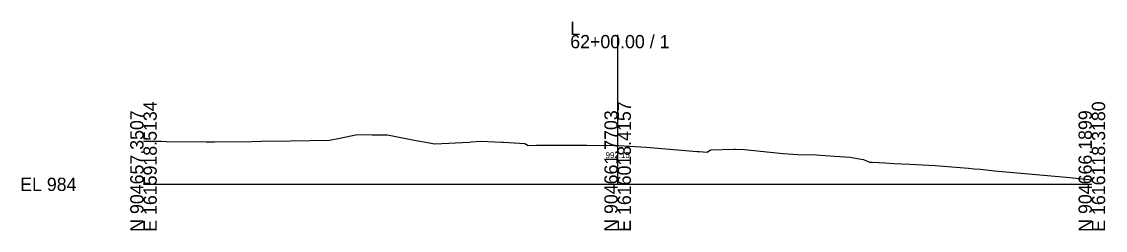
# Model space of a CAD drawing. Extents: x 1009 to 7438, y -1586 to 7964.
# Drawn here: x 6009.2 to 6237.7, y -86 to -42 of the extents above; entities that cross this region are included whole.
import ezdxf

# ---------------------------------------------------------------- set-up
doc = ezdxf.new("R2010")
doc.units = 0
for name, color, linetype in [('Exist Cross Section Cell', 7, 'Continuous'), ('Exist XS Center Line Elevation Label', 7, 'Continuous'), ('Exist XS Ground Line', 7, 'Continuous')]:
    doc.layers.add(name, color=color, linetype=linetype)

msp = doc.modelspace()

# ---------------------------------------------------------------- linework, layer by layer
at = {"layer": 'Exist Cross Section Cell'}
for p, q in [((6134.89, -76.27), (6134.89, -44.79)), ((6034.89, -76.27), (6134.89, -76.27)), ((6134.89, -76.27), (6234.89, -76.27))]:
    msp.add_line(p, q, dxfattribs=at)
at = {"layer": 'Exist XS Ground Line'}
for p, q in [((6076.29, -66.54), (6079.98, -65.78)), ((6079.98, -65.78), (6083.15, -65.81)), ((6083.15, -65.81), (6086.38, -65.87)), ((6086.38, -65.87), (6091.62, -66.91)), ((6034.89, -67.19), (6038.53, -67.2)), ((6038.53, -67.2), (6039.76, -67.21)), ((6039.76, -67.21), (6048.12, -67.33)), ((6048.12, -67.33), (6049.77, -67.33)), ((6049.77, -67.33), (6057.71, -67.23)), ((6057.71, -67.23), (6059.78, -67.2)), ((6059.78, -67.2), (6065.9, -67.09)), ((6065.9, -67.09), (6074.13, -66.95)), ((6074.13, -66.95), (6076.29, -66.54)), ((6091.62, -66.91), (6096.36, -67.75)), ((6096.36, -67.75), (6103.67, -67.36)), ((6103.67, -67.36), (6103.98, -67.33)), ((6103.98, -67.33), (6106.05, -67.2)), ((6106.05, -67.2), (6110.48, -67.35)), ((6110.48, -67.35), (6110.82, -67.36)), ((6110.82, -67.36), (6115.34, -67.63)), ((6115.34, -67.63), (6116.01, -68.09)), ((6116.01, -68.09), (6117.78, -68)), ((6117.78, -68), (6128, -68.01)), ((6128, -68.01), (6128.36, -68.01)), ((6128.36, -68.01), (6135.11, -68.12)), ((6135.11, -68.12), (6140.89, -68.47)), ((6140.89, -68.47), (6151.63, -69.35)), ((6151.63, -69.35), (6152.08, -69.38)), ((6152.08, -69.38), (6153.75, -69.48)), ((6153.75, -69.48), (6154.46, -69.02)), ((6154.46, -69.02), (6159.45, -68.88)), ((6159.45, -68.88), (6159.77, -68.89)), ((6159.77, -68.89), (6161.62, -68.96)), ((6161.62, -68.96), (6167.03, -69.51)), ((6167.03, -69.51), (6169.82, -69.8)), ((6169.82, -69.8), (6172.86, -69.95)), ((6172.86, -69.95), (6176.73, -70.06)), ((6176.73, -70.06), (6180.6, -70.32)), ((6180.6, -70.32), (6183.92, -70.51)), ((6183.92, -70.51), (6185.84, -70.89)), ((6185.84, -70.89), (6186.73, -71.04)), ((6186.73, -71.04), (6188.03, -71.6)), ((6188.03, -71.6), (6188.54, -71.57)), ((6188.54, -71.57), (6189.94, -71.64)), ((6189.94, -71.64), (6191.2, -71.72)), ((6191.2, -71.72), (6193.13, -71.9)), ((6193.13, -71.9), (6196.5, -72)), ((6196.5, -72), (6201.85, -72.32)), ((6201.85, -72.32), (6208.86, -72.87)), ((6208.86, -72.87), (6210.08, -72.97)), ((6210.08, -72.97), (6211.38, -73.09)), ((6211.38, -73.09), (6214.33, -73.44)), ((6214.33, -73.44), (6228.67, -74.68)), ((6228.67, -74.68), (6230.26, -74.83)), ((6230.26, -74.83), (6234.89, -75.34))]:
    msp.add_line(p, q, dxfattribs=at)

# ---------------------------------------------------------------- texts
at = {"layer": 'Exist Cross Section Cell'}
for s, p in [('L', (6124.89, -44.79)), ('62+00.00 / 1', (6124.89, -47.59)), ('EL 984', (6008.89, -77.67))]:
    msp.add_text(s, height=2.8, dxfattribs=at).set_placement(p)
for s, p in [('E 1615918.5134', (6037.69, -86.27)), ('E 1616018.4157', (6137.69, -86.27)), ('E 1616118.3180', (6237.69, -86.27)), ('N 904657.3507', (6034.89, -86.27)), ('N 904661.7703', (6134.89, -86.27)), ('N 904666.1899', (6234.89, -86.27))]:
    msp.add_text(s, height=2.8, rotation=90, dxfattribs=at).set_placement(p)
at = {"layer": 'Exist XS Center Line Elevation Label'}
msp.add_text('992.15', height=1.25, dxfattribs=at).set_placement((6132.34, -70.74))

doc.saveas('drawing.dxf')
